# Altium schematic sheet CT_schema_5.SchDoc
size 278 x 170 mm
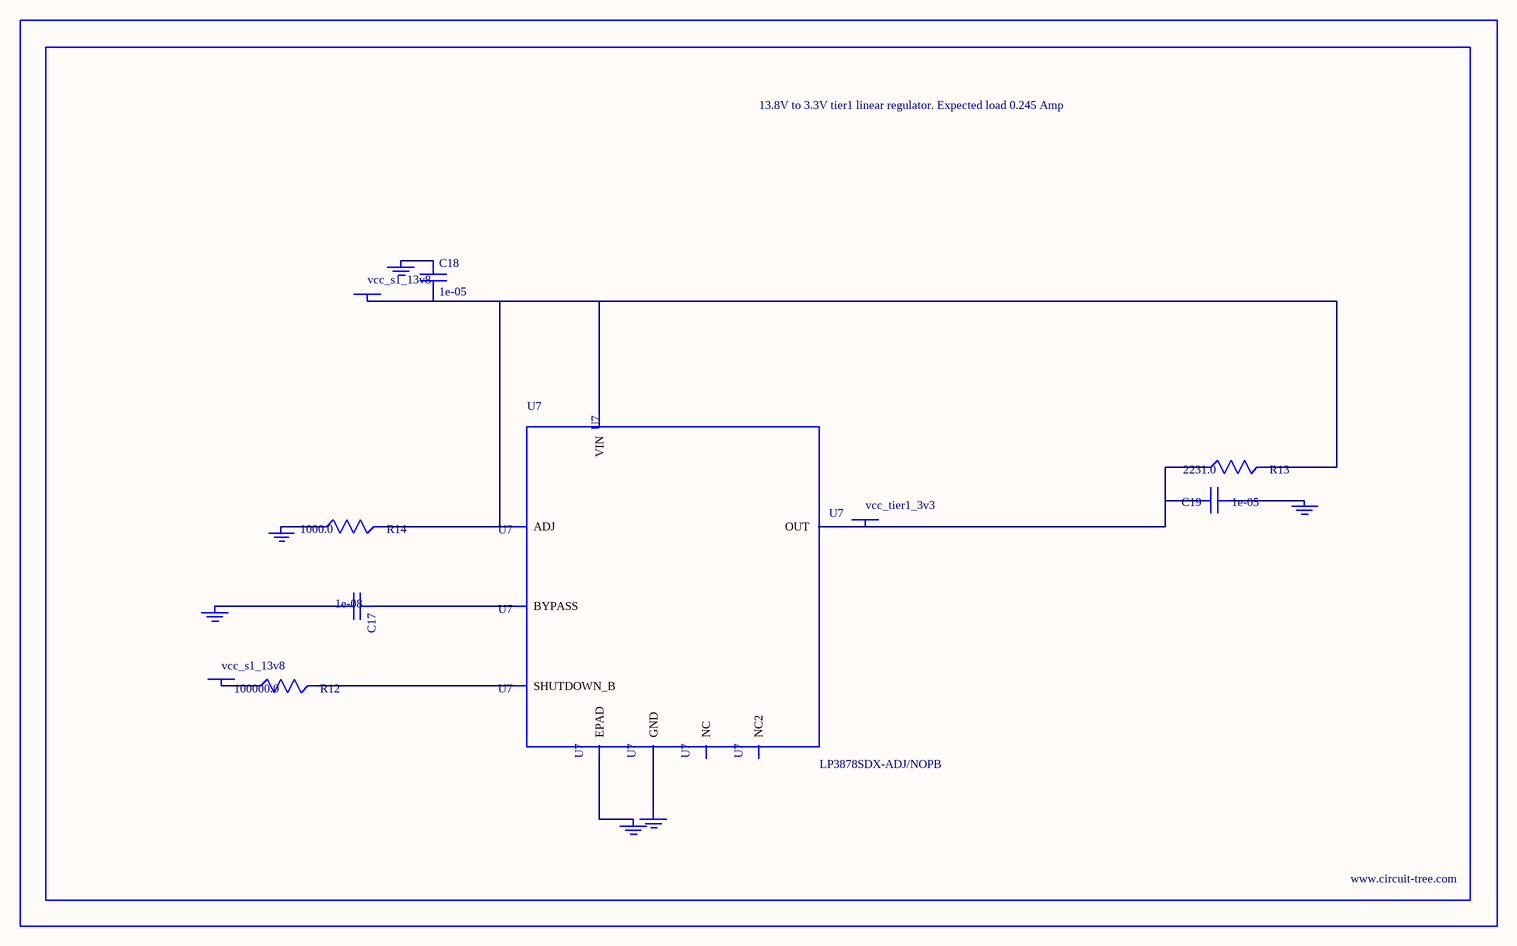
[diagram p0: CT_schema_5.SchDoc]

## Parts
BORDER4  (no value)
C17  1e-08  [C0402]
C18  1e-05  [C1210]
C19  1e-05  [C1210]
GND_INSTANCE_4_0  (no value)
GND_INSTANCE_4_1  (no value)
GND_INSTANCE_4_2  (no value)
GND_INSTANCE_4_3  (no value)
GND_INSTANCE_4_4  (no value)
GND_INSTANCE_4_5  (no value)
POWER_INSTANCE_4_0  vcc_s1_13v8
POWER_INSTANCE_4_1  vcc_s1_13v8
POWER_INSTANCE_4_2  vcc_tier1_3v3
R12  100000.0  [R0603]
R13  2231.0  [R0603]
R14  1000.0  [R0603]
U7  LP3878SDX-ADJ/NOPB  [WSON-8]

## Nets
NetC17_1: C17.1 U7.1(BYPASS)
NetC17_2: C17.2 GND_INSTANCE_4_0.0(GND)
NetC18_1: C18.1 GND_INSTANCE_4_1.0(GND)
NetC18_2: C18.2 POWER_INSTANCE_4_0.0(PWR) R13.2 R14.2 U7.4(VIN) U7.6(ADJ)
NetC19_1: C19.1 GND_INSTANCE_4_2.0(GND)
NetC19_2: C19.2 POWER_INSTANCE_4_2.0(PWR) R13.1 U7.5(OUT)
NetGND_INSTANCE_4_3_0: GND_INSTANCE_4_3.0(GND) R14.1
NetGND_INSTANCE_4_4_0: GND_INSTANCE_4_4.0(GND) U7.PAD(EPAD)
NetGND_INSTANCE_4_5_0: GND_INSTANCE_4_5.0(GND) U7.3(GND)
NetPOWER_INSTANCE_4_1_0: POWER_INSTANCE_4_1.0(PWR) R12.1
NetR12_2: R12.2 U7.8(SHUTDOWN_B)

Not connected (* = marked no-connect by the designer): U7 2(NC) 7(NC2)

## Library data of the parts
BORDER4 = BORDER_PAGE4
C17 = C0402C103K3RAC
C18 = C1210C106K5PACTU
C19 = GRM32DR61E106MA12L
GND_INSTANCE_4_0-GND_INSTANCE_4_5 = GND
POWER_INSTANCE_4_0-POWER_INSTANCE_4_2 = PWR
R12 = RC0603JR-07100KL
R13 = R13
R14 = RC0603JR-071KL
